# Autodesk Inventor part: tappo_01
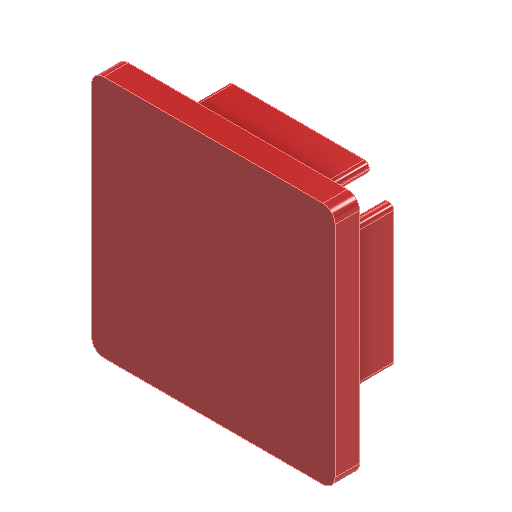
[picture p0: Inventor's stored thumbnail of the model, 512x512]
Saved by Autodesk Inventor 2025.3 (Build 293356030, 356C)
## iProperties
Created: 2026-02
Part Number: tappo_01
Material: Generico
Document SubType Name: Modeling
Designer: R5800u
Density: 1 g/cm^3
Appearance: Rosso
Author: R5800u
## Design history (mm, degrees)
sketch "Schizzo1"
  geometry: L1 (10, 10)-(-10, 10); L2 (-10, 10)-(-10, -10); L3 (-10, -10)-(10, -10); L4 (10, -10)-(10, 10); L5 (10, 10)-(-10, -10); L6 (-10, 10)-(10, -10); L7 (6, -8)-(3, -8) reference; L8 (6, -7.061)-(6, -8) reference; L9 (2.939, -4)-(6, -7.061) reference; L10 (0, 0)-(0, -10); L11 (2.939, -4)-(0, -4); L12 (3, -8)-(0, -8); L13 (0, -7.8)-(3, -7.8); L14 (3, -7.8)-(5.8, -7.8); L15 (5.8, -7.8)-(5.8, -7.144); L16 (5.8, -7.144)-(2.856, -4.2); L17 (2.856, -4.2)-(0, -4.2); L18 (0, -7.8)-(-3, -7.8); L19 (-3, -7.8)-(-5.8, -7.8); L20 (-5.8, -7.8)-(-5.8, -7.144); L21 (-5.8, -7.144)-(-2.856, -4.2); L22 (-2.856, -4.2)-(0, -4.2)
  constraints: 38 end point, 4 symmetric about line, 3 midpoint, 3 perpendicular, 2 parallel, 2 point on line, 1 horizontal, 4 other
  dimensions: "d0" = 20 distance of L3.end L2.end; "d1" = 20 distance of L2.end L1.end; "d2" = 0.2 distance between parallel lines of L12 L13
  node "Riferimento1"
  node "Riferimento2"
  node "Riferimento3"
extrude "Estrusione1" new body sketch "Schizzo1" distance "d3" = 2; taper "d4" = 0 deg
extrude "Estrusione2" new body sketch "Schizzo1" distance "d5" = 1.9; taper "d6" = 0 deg; dims "d11" = 5, "d12" = 0
pattern_circular "Serie circolare1" dims angle "d8" = 360 deg
fillet "Raccordo2" dims "d13" = 0.4
fillet "Raccordo1" dims "d10" = 1
node "Solido1"
node "Solido2"
